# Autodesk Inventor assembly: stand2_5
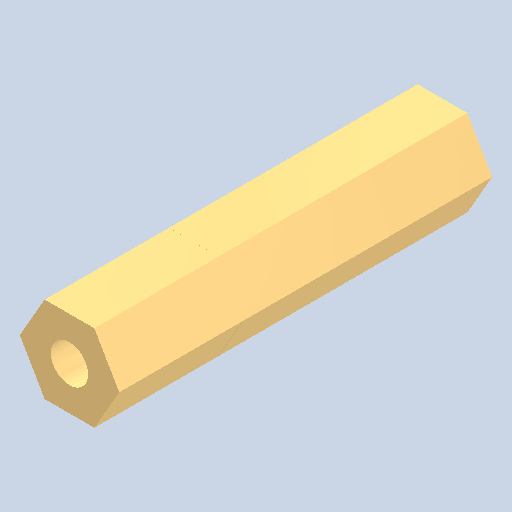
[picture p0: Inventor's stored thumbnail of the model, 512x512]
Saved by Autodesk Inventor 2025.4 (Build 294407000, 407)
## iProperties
Created: 2026-09
Part Number: stand2_5
Document SubType Name: Assembly
Designer: AdminForWorker
Title: stanofff v1
Author: AdminForWorker
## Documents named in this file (3)
- c:\worker\convert-fusion-r05-cosv3\tmp\job-1\19\temp\files\ca3d996b-dda0-445d-8bee-12a194174ca8\stanofff v1_5.iam
- c:\worker\convert-fusion-r05-cosv3\tmp\job-1\19\temp\files\ca3d996b-dda0-445d-8bee-12a194174ca8\M3-10 v1 (2).ipt
- c:\worker\convert-fusion-r05-cosv3\tmp\job-1\19\temp\files\ca3d996b-dda0-445d-8bee-12a194174ca8\M3-20 v1.ipt
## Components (2 placed, 2 different names)
1. M3-10 v1 (2):1
2. M3-20 v1:1
